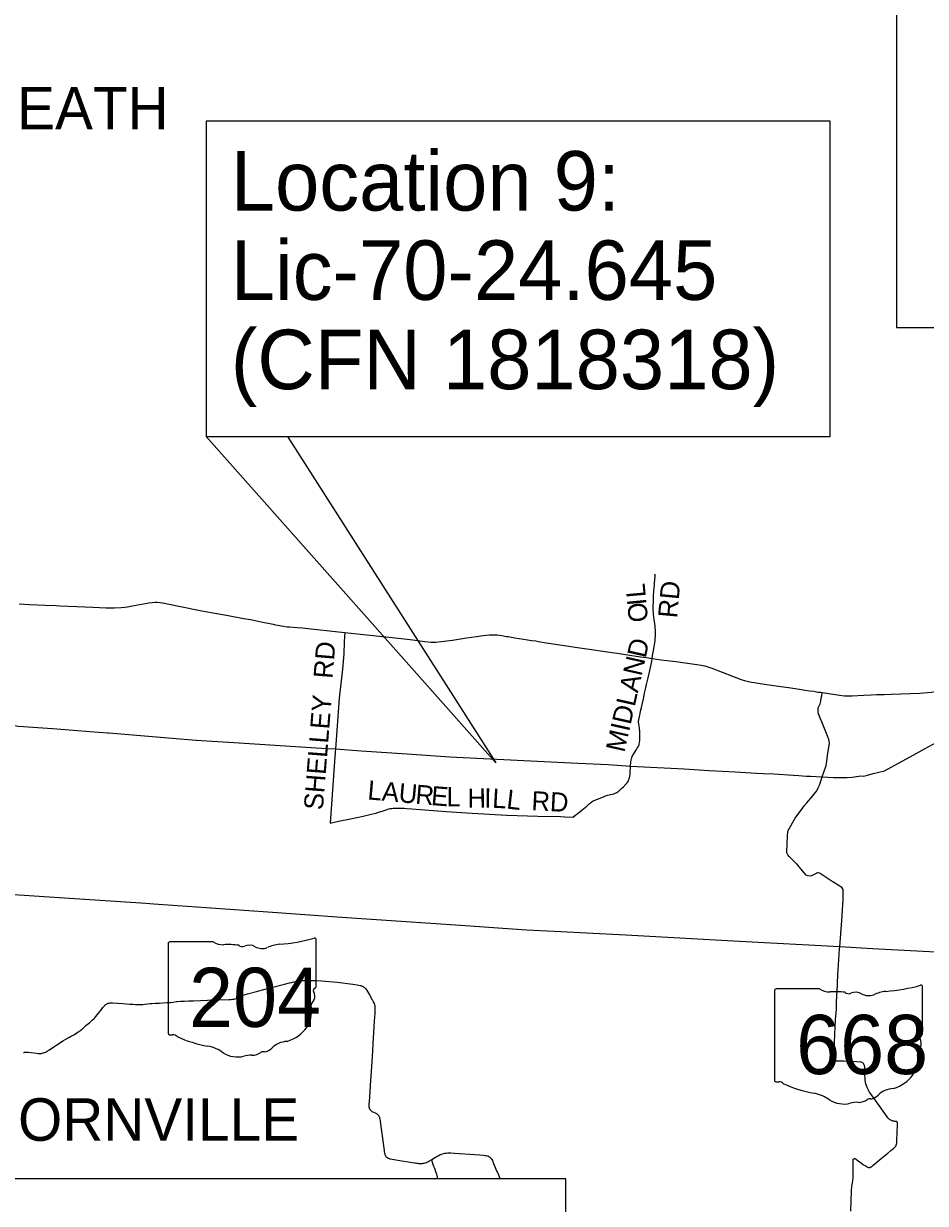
# Model space of a CAD drawing. Extents: x 1761803 to 2441803, y 509895 to 949895.
# Drawn here: x 1999264 to 2041709, y 780187 to 835674 of the extents above; entities that cross this region are included whole.
import ezdxf

# ---------------------------------------------------------------- set-up
doc = ezdxf.new("R2010")
doc.units = 0
for name, color, linetype in [('Default', 7, 'Continuous'), ('GM_X_County', 7, 'Continuous'), ('GM_X_County_Road', 7, 'Continuous'), ('GM_X_Minor_Lake', 7, 'Continuous'), ('GM_X_Minor_River', 7, 'Continuous'), ('GM_X_Minor_River_Text', 7, 'Continuous'), ('GM_X_State_Location', 7, 'Continuous'), ('GM_X_Township_Road', 7, 'Continuous')]:
    doc.layers.add(name, color=color, linetype=linetype)

msp = doc.modelspace()

# ---------------------------------------------------------------- linework, layer by layer
at = {"layer": 'Default'}
msp.add_lwpolyline([(1995413, 766506), (2024789, 766506), (2024789, 781340), (1995413, 781340)], close=True, dxfattribs=at)
at = {"layer": 'GM_X_County'}
msp.add_lwpolyline([(2049569, 791542), (2047556, 791686), (2047530, 791687), (2047510, 791689), (2047466, 791690), (2045100, 791816), (2043100, 791951), (2040417, 792097), (2039211, 792158), (2037684, 792249), (2032964, 792511), (2027603, 792795), (2024237, 792978), (2022930, 793031), (2019826, 793250), (2014237, 793633), (2010765, 793883), (2005388, 794262), (2005010, 794291), (1999991, 794615), (1998340, 794731)], dxfattribs=at)
at = {"layer": 'GM_X_County_Road'}
for points in [[(2028968, 806535), (2028989, 806672), (2028997, 806762), (2029005, 806867), (2029007, 806998), (2029005, 807080), (2029000, 807160), (2028994, 807234), (2028982, 807346), (2028969, 807440), (2028951, 807553), (2028935, 807660), (2028926, 807733), (2028919, 807790), (2028912, 807863), (2028905, 807989), (2028902, 808059), (2028902, 808130), (2028901, 808228), (2028901, 808299), (2028909, 808437), (2028914, 808618), (2028916, 808765), (2028918, 808842), (2028923, 808906), (2028929, 808992), (2028942, 809138), (2028953, 809264), (2028960, 809331), (2028980, 809559), (2028987, 809643), (2028987, 809697), (2028987, 809732), (2028980, 809773)], [(2014391, 807033), (2014374, 806840), (2014360, 806594), (2014333, 806040), (2014278, 805309), (2014122, 803951), (2013937, 801558), (2013927, 801407), (2013691, 798072)], [(2028844, 805811), (2028884, 806028), (2028924, 806274), (2028959, 806475), (2028968, 806535)], [(2028257, 802464), (2028255, 802487), (2028247, 802566), (2028236, 802629), (2028215, 802759), (2028209, 802804), (2028206, 802845), (2028214, 802931), (2028230, 803010), (2028278, 803227), (2028305, 803343), (2028347, 803515), (2028434, 803912), (2028495, 804177), (2028526, 804310), (2028587, 804591), (2028660, 804908), (2028738, 805251), (2028794, 805525), (2028827, 805696), (2028844, 805811)], [(2027625, 799921), (2027666, 799966), (2027701, 800018), (2027728, 800068), (2027749, 800117), (2027764, 800153), (2027783, 800208), (2027801, 800283), (2027812, 800354), (2027820, 800406), (2027836, 800748), (2027850, 800959), (2027862, 801037), (2027876, 801098), (2027888, 801145), (2027911, 801206), (2027979, 801338), (2028077, 801481), (2028147, 801593), (2028183, 801654), (2028222, 801731), (2028233, 801760), (2028242, 801794), (2028259, 801864), (2028273, 801961), (2028275, 802034), (2028273, 802184), (2028275, 802321), (2028264, 802408), (2028257, 802464)], [(2025142, 798359), (2025179, 798391), (2025537, 798684), (2025772, 798876), (2025802, 798904), (2025866, 798960), (2025900, 798988), (2025989, 799057), (2026028, 799084), (2026076, 799112), (2026119, 799136), (2026171, 799158), (2026227, 799181), (2026329, 799221), (2026436, 799264), (2026554, 799307), (2026652, 799348), (2026767, 799381), (2026890, 799414), (2027050, 799455), (2027103, 799475), (2027148, 799496), (2027192, 799518), (2027233, 799544), (2027265, 799568), (2027298, 799594), (2027324, 799615), (2027348, 799639)], [(2027348, 799639), (2027423, 799712), (2027495, 799783), (2027625, 799921)], [(2013691, 798072), (2014084, 798159), (2014650, 798270), (2015249, 798402), (2015620, 798495), (2015765, 798531), (2015863, 798547), (2015965, 798579), (2016139, 798638), (2016324, 798698), (2016404, 798731), (2016466, 798745), (2016512, 798753), (2016590, 798767), (2016653, 798775), (2016741, 798779), (2016811, 798778), (2016893, 798776), (2016994, 798776), (2017042, 798780), (2017084, 798774), (2017126, 798772), (2017182, 798768), (2017299, 798764), (2017531, 798747), (2019152, 798614), (2020382, 798544), (2022013, 798445), (2023466, 798394), (2024527, 798385), (2024737, 798374), (2025142, 798359)]]:
    msp.add_lwpolyline(points, dxfattribs=at)
at = {"layer": 'GM_X_Minor_Lake'}
for points in [[(2036848, 800242), (2036848, 800242), (2036929, 800475), (2037033, 800783), (2037071, 800985), (2037106, 801255), (2037198, 801833), (2037186, 801920), (2037168, 802002), (2037118, 802134), (2036826, 802843), (2036749, 803012), (2036702, 803148), (2036683, 803203), (2036666, 803300), (2036658, 803369), (2036658, 803429), (2036667, 803490), (2036749, 803687), (2036780, 803801), (2036787, 803846), (2036818, 804006), (2036833, 804065), (2036855, 804209)], [(2036325, 799268), (2036519, 799489), (2036591, 799595), (2036662, 799729), (2036718, 799852), (2036769, 799999), (2036848, 800242)], [(2035667, 796139), (2035648, 796158), (2035417, 796371), (2035297, 796500), (2035233, 796577), (2035193, 796672), (2035183, 796724), (2035214, 797470), (2035232, 797640), (2035248, 797719), (2035580, 798306), (2035935, 798785), (2036004, 798880), (2036128, 799027), (2036215, 799141), (2036325, 799268)], [(2036580, 795713), (2036571, 795709), (2036341, 795585), (2036281, 795576), (2036170, 795593), (2036093, 795619), (2035772, 796017), (2035721, 796085), (2035667, 796139)], [(2037675, 792250), (2037768, 793484), (2037833, 794485), (2037833, 794703), (2037841, 794947), (2037786, 795033), (2037674, 795114), (2037315, 795328), (2036751, 795700), (2036674, 795738), (2036627, 795734), (2036580, 795713)], [(2038202, 779829), (2038213, 780293), (2038233, 780794), (2038237, 780859), (2038241, 780915), (2038247, 780979), (2038262, 781082), (2038291, 781252), (2038297, 781299), (2038305, 781353), (2038310, 781404), (2038313, 781448), (2038315, 781517), (2038315, 781726), (2038310, 781998), (2038305, 782242), (2038312, 782260), (2038316, 782265), (2038323, 782274), (2038335, 782282), (2038346, 782287), (2038358, 782290), (2038371, 782292), (2038383, 782292), (2038395, 782291), (2038405, 782287), (2038420, 782280), (2038445, 782266), (2038487, 782234), (2038546, 782187), (2038650, 782106), (2038711, 782062), (2038792, 782007), (2038867, 781962), (2038917, 781932), (2038951, 781914), (2038986, 781897), (2039007, 781889), (2039032, 781883), (2039060, 781879), (2039083, 781880), (2039103, 781883), (2039129, 781891), (2039147, 781900), (2039171, 781913), (2039198, 781933), (2039235, 781962), (2039621, 782295), (2039776, 782426), (2039937, 782553), (2040081, 782672), (2040159, 782735), (2040209, 782776), (2040249, 782812), (2040287, 782850), (2040310, 782879), (2040322, 782896), (2040332, 782915), (2040339, 782935), (2040347, 782963), (2040352, 782989), (2040356, 783026), (2040362, 783117), (2040375, 783548), (2040388, 783860), (2040391, 783914), (2040392, 783958), (2040392, 783977), (2040390, 783991), (2040386, 784005), (2040378, 784018), (2040369, 784026), (2040359, 784031), (2040347, 784035), (2040331, 784037), (2040305, 784040), (2040273, 784043), (2040241, 784048), (2040213, 784054), (2040183, 784061), (2040151, 784071), (2040117, 784083), (2040084, 784097), (2040047, 784117), (2040012, 784140), (2039985, 784162), (2039964, 784182), (2039941, 784209), (2039687, 784574), (2039370, 785013), (2039117, 785363), (2039089, 785401), (2039064, 785439), (2039027, 785509), (2038973, 785640), (2038906, 785816), (2038893, 785862), (2038883, 785908), (2038874, 785983), (2038869, 786075), (2038864, 786205), (2038855, 786498), (2038855, 786558), (2038852, 786612), (2038848, 786652), (2038841, 786680), (2038830, 786711), (2038816, 786739), (2038798, 786763), (2038780, 786783), (2038754, 786803), (2038725, 786816), (2038687, 786827), (2038637, 786832), (2038488, 786841), (2038269, 786853), (2038042, 786864), (2037863, 786872), (2037755, 786876), (2037694, 786878), (2037623, 786878), (2037581, 786879), (2037520, 786879), (2037484, 786878), (2037461, 786879), (2037446, 786882), (2037429, 786888), (2037416, 786894), (2037407, 786899), (2037399, 786907), (2037392, 786916), (2037386, 786927), (2037380, 786941), (2037375, 786957), (2037374, 786977), (2037376, 787020), (2037379, 787066), (2037385, 787123), (2037404, 787299), (2037416, 787423), (2037422, 787537), (2037432, 787761), (2037447, 788137), (2037484, 788819), (2037506, 789143), (2037517, 789326), (2037526, 789510), (2037527, 789620), (2037536, 789942), (2037568, 790459), (2037572, 790543), (2037592, 790929), (2037614, 791409), (2037648, 791901), (2037668, 792152), (2037675, 792250)], [(1999261, 787279), (1999286, 787290), (1999304, 787296), (1999324, 787300), (1999343, 787302), (1999374, 787302), (1999414, 787300), (1999478, 787295), (1999624, 787277), (1999895, 787245), (1999946, 787240), (1999984, 787237), (2000021, 787235), (2000050, 787235), (2000077, 787236), (2000111, 787241), (2000142, 787248), (2000185, 787261), (2000240, 787280), (2000268, 787291), (2000289, 787301), (2000320, 787317), (2000369, 787343), (2000483, 787413), (2000683, 787545), (2000827, 787640), (2001137, 787841), (2001254, 787914), (2001399, 787997), (2001479, 788040), (2001520, 788060), (2001570, 788086), (2001654, 788134), (2001770, 788205), (2001838, 788249), (2001873, 788272), (2001907, 788296), (2001955, 788331), (2001988, 788359), (2002039, 788402), (2002201, 788546), (2002380, 788701), (2002505, 788813), (2002567, 788869), (2002614, 788918), (2002671, 788982), (2002733, 789053), (2002928, 789302), (2003000, 789394), (2003038, 789441), (2003064, 789470), (2003087, 789497), (2003110, 789518), (2003135, 789539), (2003161, 789558), (2003187, 789574), (2003211, 789586), (2003238, 789597), (2003268, 789606), (2003298, 789611), (2003342, 789617), (2003389, 789618), (2003428, 789617), (2003466, 789615), (2003687, 789599), (2003939, 789583), (2004266, 789564), (2004399, 789554), (2004530, 789543), (2004620, 789539), (2004682, 789538), (2004739, 789542), (2004784, 789543), (2004877, 789549), (2004973, 789558), (2005095, 789569), (2005227, 789584), (2005309, 789590), (2005455, 789600), (2005658, 789611), (2005996, 789628), (2006112, 789636), (2006184, 789641), (2006304, 789655), (2006449, 789675), (2006492, 789680), (2006642, 789692), (2006835, 789705), (2007045, 789716), (2007263, 789721), (2007913, 789745), (2008377, 789762), (2008945, 789777), (2009038, 789783), (2009095, 789789), (2009171, 789799), (2009217, 789812), (2009263, 789826), (2009368, 789871), (2009531, 789942), (2009609, 789976), (2009692, 790007), (2009807, 790044), (2010284, 790176), (2010511, 790236), (2010875, 790331), (2011549, 790499), (2011786, 790556), (2011870, 790576), (2011979, 790604), (2012077, 790627), (2012144, 790640), (2012198, 790648), (2012258, 790656), (2012319, 790661), (2012391, 790666), (2012498, 790670), (2012606, 790673), (2012838, 790670), (2013002, 790665), (2013292, 790647), (2014028, 790587), (2014761, 790490), (2014958, 790464), (2015102, 790439), (2015135, 790430), (2015166, 790421), (2015190, 790411), (2015218, 790397), (2015249, 790380), (2015278, 790362), (2015304, 790341), (2015327, 790319), (2015344, 790302), (2015369, 790275), (2015396, 790235), (2015542, 789988), (2015677, 789753), (2015679, 789748), (2015713, 789687), (2015739, 789636), (2015757, 789594), (2015781, 789525), (2015792, 789473), (2015795, 789439), (2015798, 789399), (2015798, 789339), (2015789, 789132), (2015770, 788764), (2015734, 788232), (2015702, 787709), (2015678, 787342), (2015647, 786860), (2015621, 786385), (2015591, 785975), (2015561, 785450), (2015524, 784966), (2015517, 784857), (2015514, 784815), (2015513, 784779), (2015516, 784737), (2015522, 784698), (2015535, 784653), (2015554, 784615), (2015565, 784597), (2015585, 784572), (2015601, 784554), (2015621, 784538), (2015651, 784516), (2015689, 784495), (2015747, 784471), (2015810, 784449), (2015846, 784433), (2015881, 784412), (2015913, 784388), (2015932, 784369), (2015952, 784347), (2015976, 784315), (2015989, 784291), (2015999, 784273), (2016010, 784239), (2016020, 784206), (2016030, 784157), (2016046, 784067), (2016084, 783799), (2016140, 783363), (2016169, 783133), (2016204, 782894), (2016234, 782673), (2016241, 782612), (2016246, 782584), (2016253, 782547), (2016262, 782518), (2016271, 782490), (2016285, 782455), (2016303, 782426), (2016320, 782399), (2016357, 782361), (2016373, 782347), (2016394, 782331), (2016415, 782319), (2016436, 782309), (2016470, 782297), (2016502, 782287), (2016533, 782281), (2016787, 782236), (2017556, 782111), (2017680, 782092)], [(2018326, 782162), (2018376, 782189), (2018472, 782246), (2018652, 782357), (2018689, 782381), (2018734, 782409), (2018771, 782429), (2018822, 782455), (2018874, 782480), (2018910, 782494)], [(2018910, 782494), (2018917, 782497), (2018981, 782519), (2019038, 782534), (2019092, 782547), (2019150, 782555), (2019238, 782562), (2019304, 782561)], [(2019304, 782561), (2019368, 782561), (2019551, 782550), (2020503, 782482), (2020741, 782464), (2020903, 782451), (2020967, 782444), (2021022, 782436), (2021081, 782426), (2021107, 782419), (2021128, 782409), (2021151, 782398), (2021179, 782382), (2021194, 782371), (2021211, 782357), (2021238, 782333), (2021260, 782309), (2021282, 782280), (2021288, 782270)], [(2017680, 782092), (2017713, 782087), (2017765, 782079), (2017808, 782073), (2017852, 782068), (2017910, 782065), (2017960, 782065), (2018045, 782070), (2018078, 782077), (2018120, 782086), (2018172, 782099), (2018224, 782116), (2018293, 782145), (2018326, 782162)], [(2018516, 782117), (2018472, 782246)], [(2018667, 781673), (2018665, 781678), (2018633, 781774), (2018615, 781827), (2018580, 781929), (2018516, 782117)], [(2021288, 782270), (2021301, 782251), (2021326, 782204), (2021356, 782138), (2021529, 781723), (2021565, 781640), (2021687, 781348), (2021689, 781341)], [(2018617, 781341), (2018628, 781343), (2018671, 781351), (2018694, 781357), (2018710, 781362), (2018723, 781370), (2018733, 781380), (2018743, 781394), (2018746, 781413), (2018746, 781430), (2018733, 781476), (2018707, 781555), (2018696, 781588), (2018667, 781673)]]:
    msp.add_lwpolyline(points, dxfattribs=at)
at = {"layer": 'GM_X_Minor_River'}
for points in [[(1998544, 802668), (1998920, 802643), (1999027, 802634), (2000623, 802514), (2001609, 802440)], [(2001609, 802440), (2002388, 802381), (2003224, 802322)], [(2037380, 800221), (2037440, 800218), (2037782, 800212), (2038030, 800218), (2038261, 800230), (2038580, 800279), (2038645, 800291), (2038799, 800276), (2038977, 800325), (2039245, 800405), (2039784, 800525), (2041126, 801274), (2041693, 801575), (2042211, 801864), (2042794, 802183), (2043605, 802562)], [(2003224, 802322), (2003277, 802319), (2007390, 801973), (2007400, 801973)], [(2007400, 801973), (2008132, 801924), (2008923, 801874), (2008923, 801874)], [(2008923, 801874), (2013515, 801584)], [(2013515, 801584), (2013515, 801584), (2013937, 801558), (2015151, 801475), (2015151, 801475)], [(2015151, 801475), (2017316, 801326), (2017316, 801326)], [(2017316, 801326), (2019322, 801189), (2025347, 800885), (2026772, 800822), (2027836, 800748), (2030355, 800626), (2031531, 800549), (2032759, 800488), (2033764, 800423), (2034068, 800405), (2034574, 800393), (2035503, 800321), (2035749, 800308), (2036099, 800287), (2036304, 800275), (2036848, 800242)], [(2036848, 800242), (2037380, 800221)]]:
    msp.add_lwpolyline(points, dxfattribs=at)
at = {"layer": 'GM_X_Minor_River_Text'}
for points in [[(1999061, 808384), (1999538, 808359), (2000286, 808328), (2000803, 808302), (2000967, 808294), (2001770, 808257), (2002528, 808226), (2003155, 808197), (2003336, 808194), (2003542, 808189), (2003862, 808209), (2004035, 808229), (2004150, 808246), (2004475, 808305), (2004981, 808403), (2005156, 808431), (2005319, 808448), (2005464, 808459), (2005545, 808459), (2005699, 808450), (2005797, 808431), (2006113, 808369), (2006488, 808296), (2007653, 808062), (2008354, 807935), (2008895, 807831), (2009611, 807694), (2009940, 807642), (2010167, 807597), (2010445, 807532), (2011006, 807426)], [(2011006, 807426), (2011058, 807416), (2011215, 807389), (2011504, 807336), (2011671, 807308), (2011775, 807301), (2012136, 807266), (2012390, 807251), (2012801, 807206), (2013946, 807080), (2014391, 807033), (2015560, 806904), (2016611, 806795), (2017456, 806704), (2018144, 806618), (2018448, 806587), (2018670, 806583), (2018931, 806607), (2019312, 806660), (2019444, 806678), (2019730, 806728), (2020110, 806786), (2020579, 806846), (2020897, 806894), (2021051, 806914), (2021200, 806927), (2021352, 806930), (2021471, 806929), (2021558, 806924), (2021641, 806912), (2021773, 806891), (2022000, 806856), (2022076, 806848), (2022389, 806793), (2022798, 806730), (2023171, 806668), (2023376, 806637), (2023506, 806611), (2023866, 806548), (2024614, 806443), (2025333, 806333), (2027289, 806044), (2028300, 805891), (2028579, 805855), (2028844, 805811), (2029274, 805751), (2029963, 805673), (2031055, 805513), (2031328, 805463), (2031662, 805360), (2032140, 805165), (2032635, 804984), (2032989, 804841), (2033086, 804809), (2033192, 804779), (2033324, 804743), (2033449, 804719), (2034131, 804605), (2034910, 804502), (2035262, 804451)], [(2035262, 804451), (2035780, 804375), (2036047, 804329), (2036247, 804295), (2036451, 804273), (2036652, 804235), (2036683, 804226), (2036774, 804233), (2036855, 804209), (2037071, 804184), (2037256, 804155), (2037473, 804128), (2037670, 804094), (2037907, 804060), (2038207, 804056)], [(2038207, 804056), (2038261, 804056), (2038810, 804082), (2039159, 804112), (2039421, 804117)], [(2039421, 804117), (2039774, 804124), (2040113, 804143), (2041450, 804185), (2041999, 804228), (2042166, 804260), (2042855, 804360)]]:
    msp.add_lwpolyline(points, dxfattribs=at)
at = {"layer": 'GM_X_State_Location'}
for points in [[(2040349, 821388), (2069725, 821388), (2069725, 836223), (2040349, 836223)], [(2007855, 816256), (2037232, 816256), (2037232, 831090), (2007855, 831090)], [(2021493, 800907), (2007855, 816256), (2011680, 816256)]]:
    msp.add_lwpolyline(points, close=True, dxfattribs=at)
at = {"layer": 'GM_X_Township_Road'}
for p, q in [((2006073, 792413), (2006073, 788187)), ((2008180, 792486), (2006142, 792486)), ((2013034, 790380), (2013034, 792591)), ((2013034, 790380), (2013034, 790380)), ((2034611, 790198), (2034611, 785971)), ((2036718, 790271), (2034680, 790271)), ((2041572, 788164), (2041572, 790375)), ((2041571, 788165), (2041572, 788164))]:
    msp.add_line(p, q, dxfattribs=at)
for centre, major_axis, start_param, end_param in [((2006153, 792422), (80.6, 0), 1.712693, 3.28349), ((2008666, 792976), (782, 0), 4.042523, 4.731795), ((2008925, 790113), (2808, 0), 1.404758, 1.657858), ((2011496, 791195), (1485, 0), 1.699011, 2.107814), ((2010555, 798248), (7382, 0), 4.814394, 5.042369), ((2012957, 792600), (77.5, 0), 6.141152, 7.989035), ((2009563, 792444), (226, 0), 3.836095, 5.185415), ((2009894, 791955), (469, 0), 0.950623, 2.079405), ((2010499, 792625), (564, 0), 4.081561, 5.145723), ((2013016, 790217), (120, 0), 1.883978, 3.671073), ((2012253, 789938), (720, 0), 5.934695, 6.695948), ((2012952, 790371), (82.9, 0), 5.05454, 6.418171), ((2034691, 790207), (80.6, 0), 1.712693, 3.28349), ((2037204, 790761), (782, 0), 4.042523, 4.731795), ((2037463, 787898), (2808, 0), 1.404758, 1.657858), ((2038432, 789740), (469, 0), 0.950623, 2.079405), ((2040034, 788980), (1485, 0), 1.699011, 2.107814), ((2039092, 796033), (7382, 0), 4.814394, 5.042369), ((2041495, 790385), (77.5, 0), 6.141152, 7.989035), ((2013312, 789454), (524, 0), 2.387724, 3.262537), ((2038100, 790229), (226, 0), 3.836095, 5.185415), ((2039037, 790410), (564, 0), 4.081561, 5.145723), ((2010968, 789173), (1846, 0), 5.101752, 6.440018), ((2006154, 788177), (81.4, 0), 3.00124, 4.508301), ((2006166, 788610), (621, 0), 4.665946, 4.897461), ((2006293, 787943), (224, 0), 0.519207, 1.627899), ((2009120, 791740), (5331, 0), 4.195997, 4.488961), ((2041554, 788002), (120, 0), 1.883978, 3.671073), ((2040791, 787723), (720, 0), 5.934695, 6.695948), ((2041489, 788156), (82.9, 0), 5.05454, 6.418171), ((2007530, 786288), (1668, 0), 0.823519, 1.323587), ((2010465, 787777), (597, 0), 4.937069, 5.64225), ((2011747, 787000), (1011, 0), 1.647645, 2.488434), ((2041850, 787239), (524, 0), 2.387724, 3.262537), ((2009334, 787922), (1058, 0), 4.026481, 4.996735), ((2009946, 786460), (870, 0), 1.495662, 1.94098), ((2010023, 787605), (564, 0), 4.691044, 5.507374), ((2010533, 787196), (159, 0), 1.147584, 2.315152), ((2039506, 786958), (1846, 0), 5.101752, 6.440018), ((2034692, 785962), (81.4, 0), 3.00124, 4.508301), ((2034704, 786395), (621, 0), 4.665946, 4.897461), ((2034831, 785728), (224, 0), 0.519207, 1.627899), ((2037657, 789525), (5331, 0), 4.195997, 4.488961), ((2036068, 784073), (1668, 0), 0.823519, 1.323587), ((2039003, 785562), (597, 0), 4.937069, 5.64225), ((2040284, 784785), (1011, 0), 1.647645, 2.488434), ((2037872, 785707), (1058, 0), 4.026481, 4.996735), ((2038484, 784245), (870, 0), 1.495662, 1.94098), ((2038561, 785390), (564, 0), 4.691044, 5.507374), ((2039071, 784981), (159, 0), 1.147584, 2.315152)]:
    msp.add_ellipse(centre, major_axis=major_axis, ratio=0.8, start_param=start_param, end_param=end_param, dxfattribs=at)

# ---------------------------------------------------------------- texts
at = {"layer": 'GM_X_County_Road'}
for s, height, rotation, p in [('HEATH', 2000, 0, (1997028, 830697)), ('L', 900, 95.085, (2028550, 808713)), ('RD', 900, 84.6275, (2030016, 807689)), ('I', 900, 95.4489, (2028585, 808347)), ('O', 900, 95.4616, (2028660, 807559)), ('RD', 900, 85.2744, (2013803, 804845)), ('MIDLAND', 900, 77.2846, (2027537, 801363)), ('SHELLEY', 900, 85.5064, (2013349, 798663)), ('L', 900, 354.9279, (2015429, 799190)), ('A', 900, 354.9276, (2016100, 799130)), ('U', 900, 354.9276, (2016889, 799060)), ('R', 900, 354.9281, (2017678, 798990)), ('E', 900, 355.2589, (2018420, 798924)), ('L', 900, 359.5944, (2019165, 798865)), ('H', 900, 0.3715, (2020159, 798796)), ('I', 900, 359.5097, (2020947, 798802)), ('L', 900, 356.8005, (2021305, 798799)), ('L', 900, 353.4217, (2021963, 798762)), ('RD', 900, 357.1296, (2023153, 798680)), ('THORNVILLE', 2000, 0, (1995440, 783132))]:
    msp.add_text(s, height=height, rotation=rotation, dxfattribs=at).set_placement(p)
at = {"layer": 'GM_X_State_Location'}
for s, p in [('Location 9:', (2009018, 826880)), ('Lic-70-24.645', (2009018, 822680)), ('(CFN 1818318)', (2009018, 818480))]:
    msp.add_text(s, height=2800, dxfattribs=at).set_placement(p)
at = {"layer": 'GM_X_Township_Road'}
for s, p in [('204', (2007052, 788485)), ('668', (2035624, 786269))]:
    msp.add_text(s, height=2784.4, dxfattribs=at).set_placement(p)

doc.saveas('drawing.dxf')
